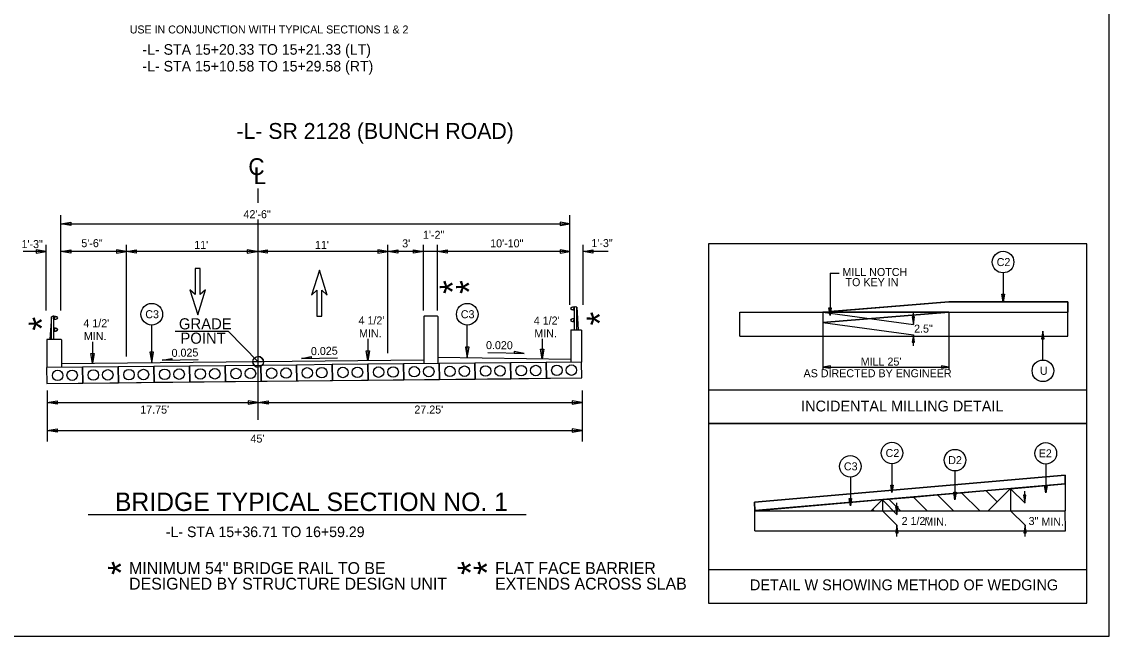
# Model space of a CAD drawing. Extents: x 574442 to 2463611, y -53527 to 675895.
# Drawn here: x 574537.4 to 574628.9, y -53527.1 to -53475.4 of the extents above; entities that cross this region are included whole.
import ezdxf

# ---------------------------------------------------------------- set-up
doc = ezdxf.new("R2010")
doc.units = 0
for name, color, linetype in [('Box Beam', 7, 'Continuous'), ('Old_Level_1', 7, 'Continuous'), ('Old_Level_11', 7, 'Continuous'), ('Old_Level_19', 7, 'Continuous'), ('Old_Level_2', 7, 'Continuous'), ('Old_Level_21', 7, 'Continuous'), ('Old_Level_23', 7, 'Continuous'), ('Old_Level_3', 7, 'Continuous'), ('Old_Level_40', 7, 'Continuous'), ('Old_Level_49', 7, 'Continuous'), ('Prop Shade Heavy', 7, 'Continuous'), ('Sheet Plot Border Outside CELL', 7, 'Continuous'), ('Typical Bridge Rail Two Bar CELL', 7, 'Continuous'), ('Typical Detail Wedge3 CELL', 7, 'Continuous'), ('Typical ID Circle CELL', 7, 'Continuous')]:
    doc.layers.add(name, color=color, linetype=linetype)

msp = doc.modelspace()

# ---------------------------------------------------------------- linework, layer by layer
at = {"layer": 'Box Beam'}
for p, q in [((574571.236, -53500.216), (574571.286, -53500.165)), ((574571.236, -53500.216), (574571.236, -53504.186)), ((574571.286, -53500.165), (574572.352, -53500.165)), ((574572.352, -53500.165), (574572.403, -53500.215)), ((574572.403, -53500.215), (574572.403, -53504.174)), ((574583.582, -53501.371), (574583.63, -53501.322)), ((574583.582, -53501.371), (574583.582, -53504.06)), ((574583.63, -53501.322), (574584.449, -53501.322)), ((574584.449, -53501.322), (574584.498, -53501.37)), ((574584.498, -53501.37), (574584.498, -53504.051)), ((574539.553, -53502.116), (574539.504, -53502.165)), ((574539.504, -53502.165), (574539.504, -53504.51)), ((574539.553, -53502.116), (574540.705, -53502.116)), ((574540.754, -53502.164), (574540.705, -53502.116)), ((574540.754, -53502.164), (574540.754, -53504.497)), ((574571.236, -53503.886), (574540.754, -53504.197)), ((574583.582, -53503.833), (574572.403, -53503.651))]:
    msp.add_line(p, q, dxfattribs=at)
for points in [[(574563.541, -53505.598), (574566.541, -53505.567), (574566.527, -53504.234), (574563.527, -53504.265)], [(574566.541, -53505.567), (574569.54, -53505.537), (574569.527, -53504.204), (574566.527, -53504.234)], [(574569.54, -53505.537), (574572.54, -53505.506), (574572.527, -53504.173), (574569.527, -53504.204)], [(574572.54, -53505.506), (574575.54, -53505.476), (574575.526, -53504.142), (574572.527, -53504.173)], [(574575.54, -53505.476), (574578.54, -53505.445), (574578.526, -53504.112), (574575.526, -53504.142)], [(574578.54, -53505.445), (574581.54, -53505.414), (574581.526, -53504.081), (574578.526, -53504.112)], [(574581.54, -53505.414), (574584.512, -53505.384), (574584.498, -53504.051), (574581.526, -53504.081)], [(574539.504, -53505.844), (574542.542, -53505.813), (574542.528, -53504.479), (574539.491, -53504.51)], [(574542.542, -53505.813), (574545.542, -53505.782), (574545.528, -53504.449), (574542.528, -53504.479)], [(574545.542, -53505.782), (574548.541, -53505.751), (574548.528, -53504.418), (574545.528, -53504.449)], [(574548.541, -53505.751), (574551.541, -53505.721), (574551.528, -53504.387), (574548.528, -53504.418)], [(574551.541, -53505.721), (574554.541, -53505.69), (574554.528, -53504.357), (574551.528, -53504.387)], [(574554.541, -53505.69), (574557.541, -53505.659), (574557.527, -53504.326), (574554.528, -53504.357)], [(574557.541, -53505.659), (574560.541, -53505.629), (574560.527, -53504.295), (574557.527, -53504.326)], [(574560.541, -53505.629), (574563.541, -53505.598), (574563.527, -53504.265), (574560.527, -53504.295)]]:
    msp.add_lwpolyline(points, close=True, dxfattribs=at)
for centre in [(574540.425, -53505.168), (574541.645, -53505.155), (574543.425, -53505.137), (574544.645, -53505.124), (574546.425, -53505.106), (574547.645, -53505.094), (574549.424, -53505.076), (574550.645, -53505.063), (574552.424, -53505.045), (574553.645, -53505.032), (574555.424, -53505.014), (574556.644, -53505.002), (574558.424, -53504.984), (574559.644, -53504.971), (574561.424, -53504.953), (574562.644, -53504.941), (574564.424, -53504.922), (574565.644, -53504.91), (574567.423, -53504.892), (574568.644, -53504.879), (574570.423, -53504.861), (574571.644, -53504.849), (574573.423, -53504.83), (574574.643, -53504.818), (574576.423, -53504.8), (574577.643, -53504.787), (574579.423, -53504.769), (574580.643, -53504.757), (574582.423, -53504.739), (574583.643, -53504.726)]:
    msp.add_circle(centre, 0.441, dxfattribs=at)
at = {"layer": 'Old_Level_1'}
for p, q in [((574605.402, -53496.555), (574606.171, -53496.555)), ((574605.402, -53496.555), (574605.402, -53500.125)), ((574619.957, -53496.541), (574619.957, -53498.965)), ((574604.803, -53499.841), (574612.412, -53500.874)), ((574615.405, -53499.84), (574615.405, -53504.699)), ((574604.803, -53500.716), (574612.412, -53501.749)), ((574604.803, -53500.716), (574604.803, -53504.699)), ((574623.309, -53503.873), (574623.309, -53501.449)), ((574604.803, -53504.464), (574615.405, -53504.464)), ((574610.612, -53512.608), (574610.612, -53515.032)), ((574615.912, -53513.208), (574615.912, -53515.632)), ((574623.548, -53512.635), (574623.548, -53515.059)), ((574607.109, -53513.729), (574607.109, -53516.153))]:
    msp.add_line(p, q, dxfattribs=at)
for centre in [(574619.957, -53495.632), (574623.309, -53504.782), (574610.612, -53511.699), (574615.912, -53512.299), (574623.548, -53511.726), (574607.109, -53512.82)]:
    msp.add_circle(centre, 0.909, dxfattribs=at)
at = {"layer": 'Old_Level_11'}
for centre in [(574548.34, -53500.021), (574574.882, -53500.021)]:
    msp.add_circle(centre, 0.909, dxfattribs=at)
at = {"layer": 'Old_Level_19'}
for p, q in [((574595.177, -53506.37), (574627, -53506.37)), ((574595.177, -53521.488), (574627, -53521.488))]:
    msp.add_line(p, q, dxfattribs=at)
for points in [[(574595.177, -53509.221), (574627, -53509.221), (574627, -53494.103), (574595.177, -53494.103)], [(574595.177, -53524.339), (574627, -53524.339), (574627, -53509.221), (574595.177, -53509.221)]]:
    msp.add_lwpolyline(points, close=True, dxfattribs=at)
at = {"layer": 'Old_Level_21'}
for p, q in [((574554.799, -53501.463), (574550.315, -53501.463)), ((574557.292, -53504.029), (574554.799, -53501.463)), ((574539.504, -53505.844), (574584.512, -53505.384)), ((574542.985, -53516.859), (574579.841, -53516.859))]:
    msp.add_line(p, q, dxfattribs=at)
at = {"layer": 'Old_Level_23'}
for p, q in [((574557.292, -53490.659), (574557.292, -53489.431)), ((574540.705, -53499.704), (574540.705, -53491.674)), ((574557.292, -53508.899), (574557.292, -53492.046)), ((574583.519, -53499.229), (574583.519, -53491.674)), ((574540.705, -53492.413), (574583.519, -53492.413)), ((574539.455, -53499.704), (574539.455, -53494.181)), ((574546.205, -53503.581), (574546.205, -53494.181)), ((574568.205, -53503.296), (574568.205, -53494.181)), ((574571.205, -53499.715), (574571.205, -53494.181)), ((574572.372, -53499.715), (574572.372, -53494.181)), ((574584.622, -53499.229), (574584.622, -53494.181)), ((574539.455, -53494.744), (574537.534, -53494.744)), ((574557.205, -53494.744), (574540.705, -53494.744)), ((574583.519, -53494.744), (574557.205, -53494.744)), ((574586.74, -53494.744), (574584.622, -53494.744)), ((574548.34, -53504.12), (574548.34, -53500.93)), ((574574.882, -53503.691), (574574.882, -53500.93)), ((574543.365, -53502.333), (574543.365, -53504.171)), ((574566.513, -53502.097), (574566.513, -53503.934)), ((574581.195, -53502.084), (574581.195, -53503.794)), ((574579.666, -53503.324), (574576.623, -53503.263)), ((574549.207, -53503.892), (574552.25, -53503.832)), ((574557.292, -53504.029), (574556.848, -53504.029)), ((574557.292, -53504.029), (574557.292, -53503.584)), ((574557.736, -53504.029), (574557.292, -53504.029)), ((574557.292, -53504.473), (574557.292, -53504.029)), ((574560.931, -53503.745), (574563.973, -53503.685)), ((574539.542, -53506.452), (574539.542, -53510.723)), ((574584.542, -53506.452), (574584.542, -53510.723)), ((574539.542, -53507.453), (574584.542, -53507.453)), ((574539.542, -53509.817), (574584.542, -53509.817))]:
    msp.add_line(p, q, dxfattribs=at)
for points in [[(574540.705, -53492.413), (574541.538, -53492.274), (574541.538, -53492.552)], [(574583.519, -53492.413), (574582.686, -53492.274), (574582.686, -53492.552)], [(574539.455, -53494.744), (574538.622, -53494.605), (574538.622, -53494.883)], [(574540.705, -53494.744), (574541.538, -53494.605), (574541.538, -53494.883)], [(574546.205, -53494.744), (574545.372, -53494.605), (574545.372, -53494.883)], [(574546.205, -53494.744), (574547.038, -53494.605), (574547.038, -53494.883)], [(574557.205, -53494.744), (574556.372, -53494.605), (574556.372, -53494.883)], [(574557.205, -53494.744), (574558.038, -53494.605), (574558.038, -53494.883)], [(574568.205, -53494.744), (574567.372, -53494.605), (574567.372, -53494.883)], [(574568.205, -53494.744), (574569.038, -53494.605), (574569.038, -53494.883)], [(574571.205, -53494.744), (574570.372, -53494.883), (574570.372, -53494.605)], [(574572.372, -53494.744), (574573.205, -53494.605), (574573.205, -53494.883)], [(574583.519, -53494.744), (574582.686, -53494.605), (574582.686, -53494.883)], [(574584.622, -53494.744), (574585.455, -53494.605), (574585.455, -53494.883)], [(574619.957, -53498.965), (574619.851, -53498.329), (574620.063, -53498.329)], [(574605.402, -53500.125), (574605.296, -53499.488), (574605.508, -53499.488)], [(574612.412, -53500.874), (574612.518, -53500.238), (574612.306, -53500.238)], [(574623.309, -53501.449), (574623.203, -53502.085), (574623.415, -53502.085)], [(574612.412, -53501.749), (574612.306, -53502.385), (574612.518, -53502.385)], [(574543.365, -53504.171), (574543.226, -53503.338), (574543.504, -53503.338)], [(574548.34, -53504.12), (574548.489, -53503.224), (574548.191, -53503.224)], [(574566.513, -53503.934), (574566.374, -53503.101), (574566.652, -53503.101)], [(574574.882, -53503.691), (574575.031, -53502.796), (574574.733, -53502.796)], [(574579.666, -53503.324), (574578.836, -53503.168), (574578.833, -53503.307)], [(574581.195, -53503.794), (574581.056, -53502.961), (574581.334, -53502.961)], [(574549.207, -53503.892), (574550.038, -53503.737), (574550.041, -53503.875)], [(574560.931, -53503.745), (574561.761, -53503.59), (574561.764, -53503.729)], [(574604.803, -53504.464), (574605.44, -53504.57), (574605.44, -53504.358)], [(574615.405, -53504.464), (574614.769, -53504.358), (574614.769, -53504.57)], [(574539.542, -53507.453), (574540.375, -53507.314), (574540.375, -53507.591)], [(574557.292, -53507.453), (574556.459, -53507.314), (574556.459, -53507.592)], [(574557.292, -53507.453), (574558.125, -53507.314), (574558.125, -53507.591)], [(574584.542, -53507.453), (574583.709, -53507.314), (574583.709, -53507.592)], [(574539.542, -53509.817), (574540.375, -53509.678), (574540.375, -53509.956)], [(574584.542, -53509.817), (574583.709, -53509.678), (574583.709, -53509.956)], [(574610.612, -53515.032), (574610.506, -53514.396), (574610.719, -53514.396)], [(574615.912, -53515.632), (574615.806, -53514.996), (574616.018, -53514.996)], [(574623.548, -53515.059), (574623.442, -53514.423), (574623.654, -53514.423)], [(574607.109, -53516.153), (574607.003, -53515.517), (574607.215, -53515.517)], [(574621.777, -53515.889), (574621.883, -53515.253), (574621.671, -53515.253)], [(574611.026, -53516.856), (574611.132, -53516.22), (574610.92, -53516.22)], [(574611.028, -53517.777), (574610.922, -53518.413), (574611.134, -53518.413)], [(574621.803, -53517.777), (574621.697, -53518.413), (574621.909, -53518.413)]]:
    msp.add_lwpolyline(points, close=True, dxfattribs=at)
msp.add_circle((574557.291, -53504.028), 0.444, dxfattribs=at)
for start, end in [(180, 270), (360, 90)]:
    msp.add_arc((574557.291, -53504.028), 0.444, start, end, dxfattribs=at)
at = {"layer": 'Old_Level_49'}
for points in [[(574552.856, -53497.962), (574552.409, -53498.374), (574552.409, -53496.174), (574551.997, -53496.174), (574551.997, -53498.374), (574551.55, -53497.962), (574552.203, -53500.059)], [(574561.788, -53498.406), (574562.235, -53497.994), (574562.235, -53500.194), (574562.648, -53500.194), (574562.648, -53497.994), (574563.094, -53498.406), (574562.441, -53496.309)]]:
    msp.add_lwpolyline(points, close=True, dxfattribs=at)
at = {"layer": 'Prop Shade Heavy'}
for p, q in [((574615.405, -53498.965), (574605.402, -53499.791)), ((574625.406, -53499.84), (574625.401, -53498.965)), ((574605.402, -53499.791), (574605.402, -53499.841)), ((574615.405, -53499.84), (574625.406, -53499.84)), ((574625.172, -53513.561), (574599.056, -53515.827)), ((574625.176, -53514.284), (574625.172, -53513.561)), ((574612.39, -53515.4), (574614.428, -53515.222)), ((574614.427, -53515.216), (574614.433, -53515.221)), ((574614.433, -53515.221), (574616.47, -53515.043)), ((574616.47, -53515.038), (574616.474, -53515.043)), ((574616.474, -53515.043), (574618.514, -53514.865)), ((574618.514, -53514.862), (574618.517, -53514.865)), ((574599.056, -53515.827), (574599.06, -53516.563)), ((574610.34, -53515.57), (574610.348, -53515.578)), ((574610.348, -53515.578), (574612.384, -53515.4)), ((574612.384, -53515.393), (574612.39, -53515.4))]:
    msp.add_line(p, q, dxfattribs=at)
for points in [[(574625.401, -53498.965), (574619.957, -53498.965), (574615.405, -53498.965)], [(574605.402, -53499.841), (574612.411, -53499.84), (574615.405, -53499.84)], [(574618.517, -53514.865), (574620.589, -53514.684), (574625.176, -53514.284)], [(574614.428, -53515.222), (574614.427, -53515.216)], [(574616.47, -53515.043), (574616.47, -53515.038)], [(574618.514, -53514.865), (574618.514, -53514.862)], [(574599.06, -53516.563), (574609.836, -53515.623), (574610.341, -53515.579)], [(574610.341, -53515.579), (574610.34, -53515.57)], [(574612.384, -53515.4), (574612.384, -53515.393)]]:
    msp.add_lwpolyline(points, dxfattribs=at)
at = {"layer": 'Sheet Plot Border Outside CELL'}
msp.add_lwpolyline([(574441.833, -53527.117), (574628.889, -53527.117), (574628.889, -53404.895), (574441.833, -53404.895)], close=True, dxfattribs=at)
at = {"layer": 'Typical Bridge Rail Two Bar CELL'}
for p, q in [((574583.834, -53499.432), (574583.834, -53499.534)), ((574583.834, -53499.636), (574583.834, -53499.534)), ((574583.877, -53499.398), (574583.952, -53499.397)), ((574583.897, -53501.322), (574583.897, -53499.4)), ((574584.086, -53499.438), (574583.972, -53499.4)), ((574584.086, -53501.322), (574584.086, -53499.438)), ((574584.086, -53499.438), (574584.223, -53501.322)), ((574539.916, -53500.232), (574539.779, -53502.116)), ((574539.916, -53500.232), (574540.03, -53500.195)), ((574539.916, -53502.116), (574539.916, -53500.232)), ((574540.105, -53500.195), (574540.03, -53500.195)), ((574540.105, -53502.116), (574540.105, -53500.195)), ((574540.168, -53500.226), (574540.168, -53500.328)), ((574540.168, -53500.431), (574540.168, -53500.328)), ((574583.834, -53500.419), (574583.834, -53500.521)), ((574583.834, -53500.623), (574583.834, -53500.521)), ((574584.086, -53500.302), (574584.09, -53500.302)), ((574539.916, -53501.096), (574539.912, -53501.096)), ((574540.168, -53501.213), (574540.168, -53501.315)), ((574540.168, -53501.418), (574540.168, -53501.315))]:
    msp.add_line(p, q, dxfattribs=at)
for centre, start, end in [((574583.826, -53499.432), 0, 90), ((574583.826, -53499.636), 270, 0), ((574540.176, -53500.226), 90, 180), ((574540.176, -53500.431), 180, 270), ((574583.826, -53500.419), 0, 90), ((574540.176, -53501.213), 90, 180), ((574540.176, -53501.418), 180, 270), ((574583.826, -53500.623), 270, 0)]:
    msp.add_arc(centre, 0.00783, start, end, dxfattribs=at)
for centre, major_axis, ratio, start_param, end_param in [((574583.897, -53499.534), (-0.334, 0), 0.39036, 4.712404, 6.283584), ((574583.897, -53499.534), (-0.334, 0), 0.39036, 0.000398, 1.570782), ((574583.826, -53499.534), (-0.222, 0), 0.495501, 4.712489, 6.283652), ((574583.826, -53499.534), (-0.222, 0), 0.495501, 0.000467, 1.570696), ((574540.105, -53500.328), (0.334, 0), 0.39036, 6.282787, 7.853967), ((574540.105, -53500.328), (0.334, 0), 0.39036, 4.712404, 6.282787), ((574540.176, -53500.328), (0.222, 0), 0.495501, 6.282718, 7.853881), ((574540.176, -53500.328), (0.222, 0), 0.495501, 4.712489, 6.282718), ((574583.897, -53500.521), (-0.334, 0), 0.39036, 4.712404, 6.283584), ((574583.897, -53500.521), (-0.334, 0), 0.39036, 0.000398, 1.570782), ((574583.826, -53500.521), (-0.222, 0), 0.495501, 4.712489, 6.283652), ((574583.826, -53500.521), (-0.222, 0), 0.495501, 0.000467, 1.570696), ((574540.105, -53501.315), (0.334, 0), 0.39036, 6.282787, 7.853967), ((574540.105, -53501.315), (0.334, 0), 0.39036, 4.712404, 6.282787), ((574540.176, -53501.315), (0.222, 0), 0.495501, 6.282718, 7.853881), ((574540.176, -53501.315), (0.222, 0), 0.495501, 4.712489, 6.282718)]:
    msp.add_ellipse(centre, major_axis=major_axis, ratio=ratio, start_param=start_param, end_param=end_param, dxfattribs=at)
at = {"layer": 'Typical Detail Wedge3 CELL'}
for p, q in [((574604.803, -53499.841), (574615.405, -53498.965)), ((574615.405, -53498.965), (574625.401, -53498.965)), ((574625.406, -53498.965), (574625.406, -53499.84)), ((574597.803, -53499.841), (574625.406, -53499.84)), ((574597.819, -53501.872), (574597.803, -53499.841)), ((574615.405, -53499.84), (574604.803, -53500.716)), ((574612.412, -53500.874), (574612.411, -53499.898)), ((574615.405, -53499.84), (574625.406, -53499.84)), ((574625.418, -53501.87), (574625.406, -53499.84)), ((574597.819, -53501.872), (574625.418, -53501.87)), ((574612.414, -53502.694), (574612.412, -53501.749)), ((574599.056, -53515.827), (574625.172, -53513.561)), ((574599.056, -53515.827), (574625.172, -53513.561)), ((574599.061, -53516.549), (574625.176, -53514.284)), ((574625.176, -53514.284), (574599.061, -53516.549)), ((574620.591, -53514.704), (574625.176, -53514.284)), ((574625.172, -53513.561), (574625.176, -53514.284)), ((574625.172, -53513.561), (574625.176, -53514.284)), ((574625.176, -53514.284), (574625.186, -53516.562)), ((574614.427, -53515.216), (574615.781, -53516.57)), ((574616.47, -53515.038), (574617.996, -53516.564)), ((574618.514, -53514.862), (574619.462, -53515.81)), ((574618.709, -53516.562), (574620.589, -53514.684)), ((574620.589, -53514.684), (574620.589, -53516.562)), ((574620.591, -53514.704), (574621.812, -53515.925)), ((574621.777, -53515.889), (574621.776, -53514.913)), ((574599.061, -53516.549), (574599.056, -53515.827)), ((574599.061, -53516.549), (574599.056, -53515.827)), ((574608.865, -53516.564), (574609.814, -53515.616)), ((574609.814, -53515.616), (574609.814, -53516.563)), ((574609.84, -53515.671), (574611.061, -53516.891)), ((574610.34, -53515.57), (574611.336, -53516.566)), ((574611.026, -53516.856), (574611.025, -53515.88)), ((574612.384, -53515.393), (574613.537, -53516.545)), ((574599.06, -53516.563), (574625.186, -53516.562)), ((574599.074, -53518.256), (574599.06, -53516.563)), ((574608.991, -53516.442), (574609.109, -53516.56)), ((574609.814, -53516.563), (574611.028, -53517.777)), ((574620.589, -53516.562), (574621.803, -53517.777)), ((574625.196, -53518.254), (574625.186, -53516.562)), ((574611.029, -53518.722), (574611.028, -53517.777)), ((574621.804, -53518.722), (574621.803, -53517.777)), ((574599.074, -53518.256), (574625.196, -53518.254))]:
    msp.add_line(p, q, dxfattribs=at)
msp.add_lwpolyline([(574615.405, -53499.84), (574604.803, -53499.841), (574604.803, -53500.716), (574615.405, -53499.84)], dxfattribs=at)
at = {"layer": 'Typical ID Circle CELL'}
for p, q in [((574610.612, -53513.159), (574610.612, -53515.032)), ((574607.109, -53514.28), (574607.109, -53516.153)), ((574615.912, -53513.758), (574615.912, -53515.632))]:
    msp.add_line(p, q, dxfattribs=at)

# ---------------------------------------------------------------- texts
at = {"layer": 'Old_Level_1'}
for s, height, p in [('C2', 0.6733, (574619.419, -53495.969)), ('MILL NOTCH', 0.6733, (574606.443, -53496.806)), ('TO KEY IN', 0.6733, (574606.703, -53497.66)), ('2.5"', 0.6733, (574612.473, -53501.569)), ("MILL 25'", 0.6733, (574607.981, -53504.343)), ('AS DIRECTED BY ENGINEER', 0.67333, (574603.172, -53505.324)), ('U', 0.673, (574623.057, -53505.118)), ('C2', 0.6733, (574610.074, -53512.036)), ('C3', 0.6733, (574606.565, -53513.157)), ('D2', 0.6733, (574615.342, -53512.635)), ('2 1/2"', 0.6733, (574611.419, -53517.757)), ('MIN.', 0.6733, (574613.332, -53517.818)), ('3"', 0.6733, (574622.105, -53517.757)), ('MIN.', 0.6733, (574623.182, -53517.818))]:
    msp.add_text(s, height=height, dxfattribs=at).set_placement(p)
msp.add_text('E2', height=0.6733, rotation=360, dxfattribs=at).set_placement((574622.957, -53512.063))
at = {"layer": 'Old_Level_19'}
for s, p in [('INCIDENTAL MILLING DETAIL', (574602.967, -53508.201)), ('DETAIL W SHOWING METHOD OF WEDGING', (574598.66, -53523.247))]:
    msp.add_text(s, height=0.909, dxfattribs=at).set_placement(p)
at = {"layer": 'Old_Level_2'}
for s, p in [('GRADE', (574550.626, -53501.296)), ('POINT', (574550.752, -53502.502))]:
    msp.add_text(s, height=0.9337, rotation=360, dxfattribs=at).set_placement(p)
at = {"layer": 'Old_Level_21'}
for s, height, p in [('42\'-6"', 0.6733, (574556.056, -53491.943)), ('1\'-2"', 0.6733, (574571.158, -53493.676)), ('1\'-3"', 0.6733, (574537.382, -53494.457)), ('5\'-6"', 0.6733, (574542.416, -53494.379)), ("11'", 0.6733, (574551.913, -53494.522)), ("11'", 0.6733, (574562.068, -53494.522)), ("3'", 0.6733, (574569.406, -53494.397)), ('10\'-10"', 0.6733, (574576.81, -53494.393)), ('1\'-3"', 0.6733, (574585.322, -53494.372)), ('C3', 0.6733, (574547.796, -53500.358)), ('C3', 0.6733, (574574.339, -53500.358)), ("4 1/2'", 0.6733, (574542.589, -53501.116)), ("4 1/2'", 0.6733, (574565.737, -53500.88)), ("4 1/2'", 0.6733, (574580.479, -53500.887)), ('MIN.', 0.6733, (574565.779, -53501.964)), ('MIN.', 0.6733, (574580.522, -53501.971)), ('MIN.', 0.6733, (574542.631, -53502.2)), ("17.75'", 0.6733, (574547.374, -53508.385)), ("27.25'", 0.6733, (574570.433, -53508.377)), ("45'", 0.6733, (574556.646, -53510.822)), ('-L- STA 15+36.71 TO 16+59.29', 0.88889, (574549.524, -53518.774))]:
    msp.add_text(s, height=height, dxfattribs=at).set_placement(p)
for s, rotation, p in [('0.020', 359.67329, (574576.458, -53502.954)), ('0.025', 1.14576, (574550.014, -53503.615)), ('0.025', 1.14576, (574561.737, -53503.468))]:
    msp.add_text(s, height=0.6733, rotation=rotation, dxfattribs=at).set_placement(p)
at = {"layer": 'Old_Level_23'}
msp.add_text('USE IN CONJUNCTION WITH TYPICAL SECTIONS 1 & 2', height=0.67, dxfattribs=at).set_placement((574546.486, -53476.396))
at = {"layer": 'Old_Level_3'}
for s, height, p in [('-L- STA 15+20.33 TO 15+21.33 (LT)', 0.88889, (574547.554, -53478.187)), ('-L- STA 15+10.58 TO 15+29.58 (RT)', 0.88889, (574547.554, -53479.596)), ('BRIDGE TYPICAL SECTION NO. 1', 1.55556, (574545.243, -53516.58))]:
    msp.add_text(s, height=height, dxfattribs=at).set_placement(p)
for s, height, p in [('-L- SR 2128 (BUNCH ROAD)', 1.33598, (574555.466, -53485.269)), ('C', 1.415, (574556.464, -53488.312)), ('L', 1.415, (574556.907, -53489.069))]:
    msp.add_text(s, height=height, rotation=360, dxfattribs=at).set_placement(p)
at = {"layer": 'Old_Level_40'}
for p in [(574574.769, -53498.315), (574576.156, -53498.315), (574540.211, -53501.398), (574587.143, -53500.965), (574546.868, -53521.953), (574576.287, -53521.953), (574577.654, -53521.953)]:
    msp.add_text('*', height=2.222, rotation=90, dxfattribs=at).set_placement(p)
for s, p in [('MINIMUM 54" BRIDGE RAIL TO BE', (574546.434, -53521.881)), ('FLAT FACE BARRIER', (574577.22, -53521.881)), ('DESIGNED BY STRUCTURE DESIGN UNIT', (574546.434, -53523.192)), ('EXTENDS ACROSS SLAB', (574577.22, -53523.192))]:
    msp.add_text(s, height=1, dxfattribs=at).set_placement(p)

doc.saveas('drawing.dxf')
